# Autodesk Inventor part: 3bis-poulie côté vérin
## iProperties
Created: 2011-02
Part Number: 3bis-poulie côté vérin
Document SubType Name: Modeling
Designer: eric
Density: 1 g/cm^3
Author: eric
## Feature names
1. Base1
